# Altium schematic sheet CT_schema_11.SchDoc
size 147 x 119 mm
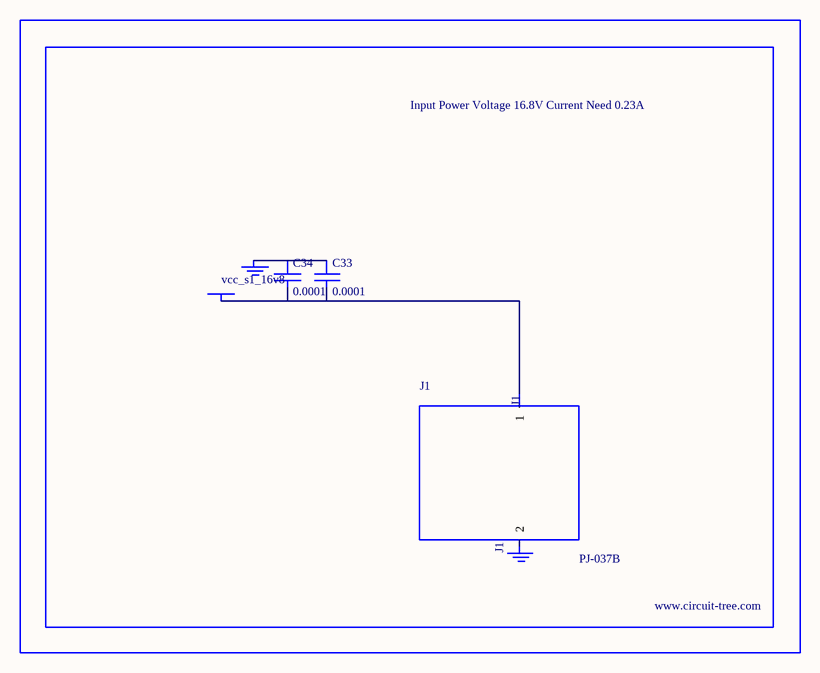
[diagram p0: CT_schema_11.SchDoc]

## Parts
BORDER10  (no value)
C33  0.0001  [EXV-9H]
C34  0.0001  [EXV-9H]
GND_INSTANCE_10_0  (no value)
GND_INSTANCE_10_1  (no value)
J1  PJ-037B  [PJ-037B_PACKAGE]
POWER_INSTANCE_10_0  vcc_s1_16v8

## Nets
NetC33_1: C33.1 C34.1 GND_INSTANCE_10_0.0(GND)
NetC33_2: C33.2 C34.2 J1.1 POWER_INSTANCE_10_0.0(PWR)

Not connected (* = marked no-connect by the designer): GND_INSTANCE_10_1 0(GND); J1 2

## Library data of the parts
BORDER10 = BORDER_PAGE10
C33 C34 = EDK107M035A9HAA
GND_INSTANCE_10_0 GND_INSTANCE_10_1 = GND
POWER_INSTANCE_10_0 = PWR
